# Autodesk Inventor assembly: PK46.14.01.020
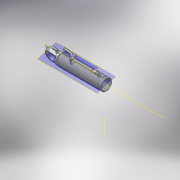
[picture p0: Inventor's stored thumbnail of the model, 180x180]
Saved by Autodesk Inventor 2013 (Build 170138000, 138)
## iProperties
Shininess: 64.0
Length Units: 11269
Angle Units: 11279
Time Units: 11290
Mass Units: 11283
Length Display Precision: 3
Angle Display Precision: 2
Compacted: True
Created: 2004-11
Part Number: PK46.14.01.020
Document SubType Name: Assembly
Designer: ELarisa
Manufacturer: Standard
Standards Organization: Custom
Density: 0.0
Volumn: 0.0
Area: 0.0
PropertySet Name: Model Information
Control State: 0
Master: False
Checked Out: False
Checked Out Date: 2008-10-15
Last Check In Date: 2008-10-15
Author: ELarisa
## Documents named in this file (9)
- C:\Product Design Suite 2013 Test Drive\Model Based Documentation\Workspace\Assemblies\PK46.14.01.020.iam
- C:\Product Design Suite 2013 Test Drive\Model Based Documentation\Workspace\Parts\PK46.14.01.002.ipt
- C:\Product Design Suite 2013 Test Drive\Model Based Documentation\Workspace\Parts\PK46.14.01.015.ipt
- C:\Product Design Suite 2013 Test Drive\Model Based Documentation\Workspace\Parts\PK46.14.01.007.ipt
- C:\Product Design Suite 2013 Test Drive\Model Based Documentation\Workspace\Parts\D395B-43-192-2.ipt
- C:\Product Design Suite 2013 Test Drive\Model Based Documentation\Workspace\Parts\PK46.14.01.016.ipt
- C:\Product Design Suite 2013 Test Drive\Model Based Documentation\Workspace\Parts\10.65G.019.ipt
- C:\Product Design Suite 2013 Test Drive\Model Based Documentation\Workspace\Assemblies\PK46.14.01.040.iam
- C:\Product Design Suite 2013 Test Drive\Model Based Documentation\Workspace\Parts\M10-6gx25.58.019(S16).ipt
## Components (11 placed, 8 different names)
1. PK46.14.01.002:1 — Insert:1, Angle:1, Insert:2, Angle:3, Insert:15, Mate:3
2. PK46.14.01.007:1 — Insert:1, Angle:1, Insert:6, Angle:9
3. D395B-43-192-2:1 — Insert:2, Angle:3, Insert:17, Angle:8, Angle:10
4. D395B-43-192-2:2 — Insert:6, Angle:10
5. PK46.14.01.040:1 [sub-assembly] — Insert:17
6. PK46.14.01.015:1 — Insert:15, Insert:16, Mate:1
7. PK46.14.01.016:1 — Insert:11, Insert:12, Insert:16, Mate:1, Angle:8
8. 10.65G.019:1 — Insert:11, Insert:13
9. 10.65G.019:2 — Insert:12, Insert:14
10. M10-6gx25.58.019(S16):1 — Insert:13
11. M10-6gx25.58.019(S16):2 — Insert:14
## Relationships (17: Insert 10, Angle 5, Mate 2)
- Insert:1: PK46.14.01.002:1 ↔ PK46.14.01.007:1
- Angle:1: PK46.14.01.002:1 ↔ PK46.14.01.007:1
- Insert:2: PK46.14.01.002:1 ↔ D395B-43-192-2:1
- Angle:3: PK46.14.01.002:1 ↔ D395B-43-192-2:1
- Insert:6: PK46.14.01.007:1 ↔ D395B-43-192-2:2
- Insert:11: PK46.14.01.016:1 ↔ 10.65G.019:1
- Insert:12: PK46.14.01.016:1 ↔ 10.65G.019:2
- Insert:13: 10.65G.019:1 ↔ M10-6gx25.58.019(S16):1
- Insert:14: 10.65G.019:2 ↔ M10-6gx25.58.019(S16):2
- Insert:15: PK46.14.01.002:1 ↔ PK46.14.01.015:1
- Insert:16: PK46.14.01.015:1 ↔ PK46.14.01.016:1
- Mate:1: PK46.14.01.015:1 ↔ PK46.14.01.016:1
- Insert:17: D395B-43-192-2:1 ↔ PK46.14.01.040:1
- Angle:8: D395B-43-192-2:1 ↔ PK46.14.01.016:1
- Mate:3: PK46.14.01.002:1
- Angle:9: PK46.14.01.007:1
- Angle:10: D395B-43-192-2:1 ↔ D395B-43-192-2:2
